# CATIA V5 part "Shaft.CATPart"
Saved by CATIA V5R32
Part number: Part2
Material "Iron": density 7870 kg/m3, Young's modulus 2.11e+11 Pa, Poisson ratio 0.291, thermal expansion 1.21e-05 1/K
Bounding box of the stored display mesh (mm): x -20.121 to 20.121, y 0 to 300, z -20.121 to 20.121
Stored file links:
  D:\PROJECTS\Project 2022\CATIA V5 6R 2022\Resources\Tutorial Files\c19_catia_v5_6r2022_tut\C19_tut_02.CATPart\Shaft.CATPart
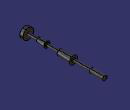
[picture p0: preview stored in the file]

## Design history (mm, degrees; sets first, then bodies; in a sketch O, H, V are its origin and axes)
Body1 (main body), material "Iron"
  Sketch1 on yz-plane, origin (0, 0, 0), H (0, 1, 0), V (0, 0, 1)
    line L1 (0, 0) -> (0, 20.127)
    line L2 (0, 20.127) -> (12.0221, 20.127)
    line L3 (12.0221, 20.127) -> (12.0221, 5.2746)
    point P3 (12.0221, 5.2746)
    line L4 (12.0221, 5.2746) -> (51.1457, 5.2746)
    line L5 (51.1457, 5.2746) -> (51.1457, 8.5349)
    line L6 (51.1457, 8.5349) -> (82.0221, 11.1079)
    line L7 (82.0221, 11.1079) -> (82.0221, 5.2746)
    point P7 (82.0221, 5.2746)
    line L8 (82.0221, 5.2746) -> (132.0221, 5.2746)
    line L9 (132.0221, 5.2746) -> (132.0221, 10.9839)
    line L10 (132.0221, 10.9839) -> (182.0221, 15.1506)
    line L11 (182.0221, 15.1506) -> (182.0221, 5.2746)
    point P11 (182.0221, 5.2746)
    line L12 (182.0221, 5.2746) -> (250, 5.2746)
    line L13 (250, 5.2746) -> (250, 8.5349)
    line L14 (250, 8.5349) -> (300, 8.5349)
    line L15 (300, 8.5349) -> (300, 0)
    point P15 (300, 0)
    axis line L16 (0, 0) -> (300, 0)
    distance L15 L1 = 300
    distance L13 L1 = 250
    distance L11 L7 = 100
    distance L3 L7 = 70
    distance L9 L11 = 50
    vertical: L1 V, L3 V, L5 V, L7 V, L9 V, L11 V, L13 V, L15 V
    horizontal: L2 H, L4 H, L8 H, L12 H, L14 H, L16 H
    coincidence: L6 P3, P7 L4, P11 L4, P15 H
    parallelism: L10 L6
  Shaft1: profile Sketch1, axis Sketch1.L16, angle 360
  Fillet1: radius 2, on edge [face of Shaft1 from Sketch1.L7 | face of Shaft1 from Sketch1.L8]; edge [face of Shaft1 from Sketch1.L4 | face of Shaft1 from Sketch1.L5]; edge [face of Shaft1 from Sketch1.L8 | face of Shaft1 from Sketch1.L9]; edge [face of Shaft1 from Sketch1.L11 | face of Shaft1 from Sketch1.L12]; edge [face of Shaft1 from Sketch1.L12 | face of Shaft1 from Sketch1.L13]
